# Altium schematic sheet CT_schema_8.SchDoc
size 277 x 170 mm
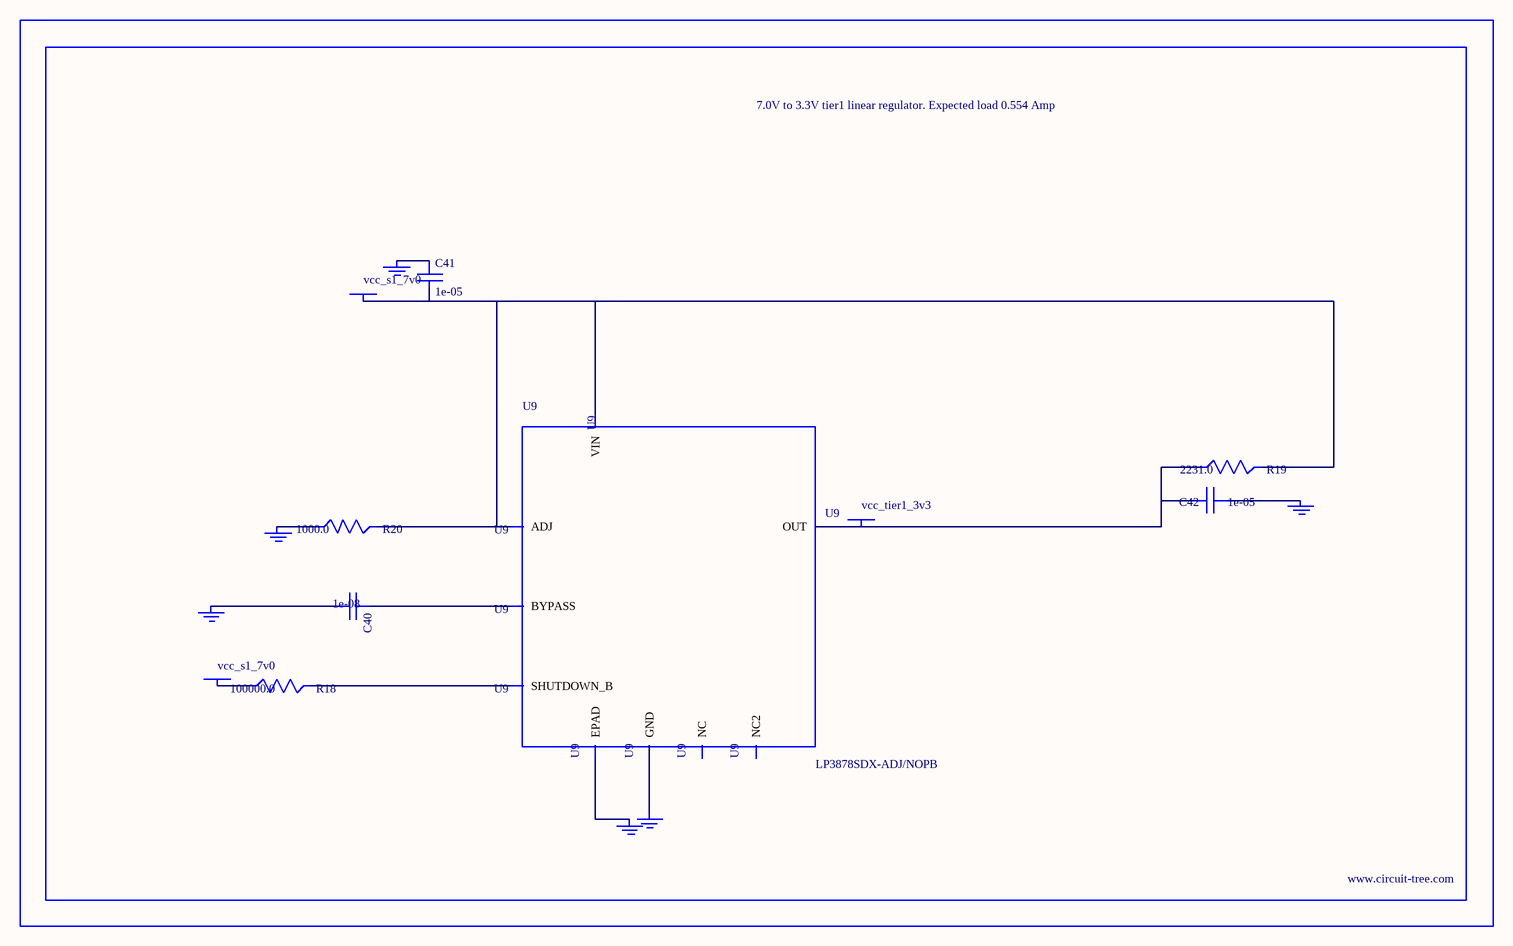
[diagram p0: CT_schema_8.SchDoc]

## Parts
BORDER7  (no value)
C40  1e-08  [C0402]
C41  1e-05  [C1206]
C42  1e-05  [C1210]
GND_INSTANCE_7_0  (no value)
GND_INSTANCE_7_1  (no value)
GND_INSTANCE_7_2  (no value)
GND_INSTANCE_7_3  (no value)
GND_INSTANCE_7_4  (no value)
GND_INSTANCE_7_5  (no value)
POWER_INSTANCE_7_0  vcc_s1_7v0
POWER_INSTANCE_7_1  vcc_s1_7v0
POWER_INSTANCE_7_2  vcc_tier1_3v3
R18  100000.0  [R0603]
R19  2231.0  [R0603]
R20  1000.0  [R0603]
U9  LP3878SDX-ADJ/NOPB  [WSON-8]

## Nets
NetC40_1: C40.1 U9.1(BYPASS)
NetC40_2: C40.2 GND_INSTANCE_7_0.0(GND)
NetC41_1: C41.1 GND_INSTANCE_7_1.0(GND)
NetC41_2: C41.2 POWER_INSTANCE_7_0.0(PWR) R19.2 R20.2 U9.4(VIN) U9.6(ADJ)
NetC42_1: C42.1 GND_INSTANCE_7_2.0(GND)
NetC42_2: C42.2 POWER_INSTANCE_7_2.0(PWR) R19.1 U9.5(OUT)
NetGND_INSTANCE_7_3_0: GND_INSTANCE_7_3.0(GND) R20.1
NetGND_INSTANCE_7_4_0: GND_INSTANCE_7_4.0(GND) U9.PAD(EPAD)
NetGND_INSTANCE_7_5_0: GND_INSTANCE_7_5.0(GND) U9.3(GND)
NetPOWER_INSTANCE_7_1_0: POWER_INSTANCE_7_1.0(PWR) R18.1
NetR18_2: R18.2 U9.8(SHUTDOWN_B)

Not connected (* = marked no-connect by the designer): U9 2(NC) 7(NC2)

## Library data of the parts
BORDER7 = BORDER_PAGE7
C40 = C0402C103K3RAC
C41 = C1206C106K3RACTU
C42 = GRM32DR61E106MA12L
GND_INSTANCE_7_0-GND_INSTANCE_7_5 = GND
POWER_INSTANCE_7_0-POWER_INSTANCE_7_2 = PWR
R18 = RC0603JR-07100KL
R19 = R19
R20 = RC0603JR-071KL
